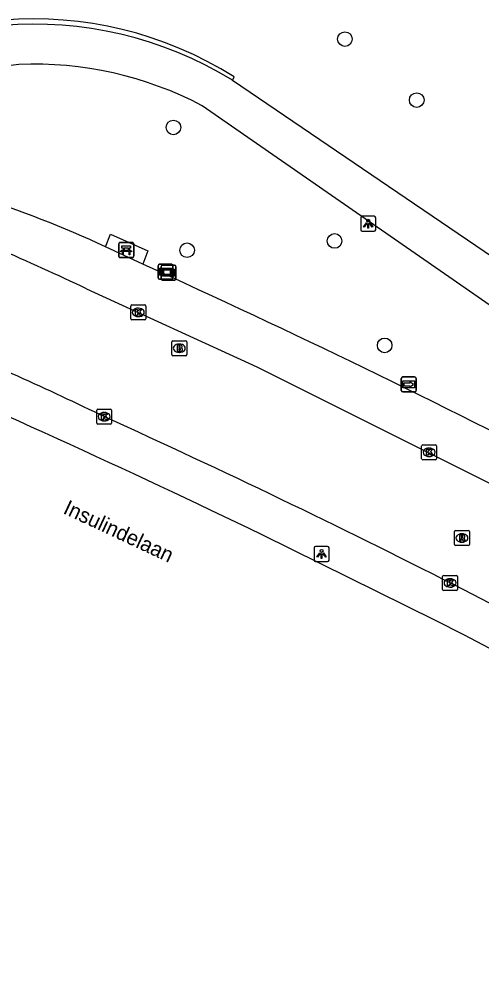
# Model space of a CAD drawing. Extents: x 162417 to 163721, y 384268 to 385416.
# Drawn here: x 162450.1 to 162481, y 384748.5 to 384811.7 of the extents above; entities that cross this region are included whole.
import ezdxf

# ---------------------------------------------------------------- set-up
doc = ezdxf.new("R2010")
doc.units = 0
for name, color, linetype in [('IMGEO_Bank', 7, 'Continuous'), ('IMGEO_Boom', 7, 'Continuous'), ('IMGEO_Brandkraan', 7, 'Continuous'), ('IMGEO_Kolk', 7, 'Continuous'), ('IMGEO_Lichtpunt', 7, 'Continuous'), ('IMGEO_Muur', 7, 'Continuous'), ('IMGEO_Openbare_ruimte_label', 7, 'Continuous'), ('IMGEO_Rijbaan_lokaal_open', 7, 'Continuous'), ('IMGEO_Rijbaan_regionaal_gesloten', 7, 'Continuous'), ('IMGEO_Rioolput', 7, 'Continuous'), ('IMGEO_Verklikker', 7, 'Continuous'), ('IMGEO_Voetpad_gesloten', 7, 'Continuous'), ('IMGEO_Voetpad_open', 7, 'Continuous'), ('IMGEO_Wegwijzer', 7, 'Continuous')]:
    doc.layers.add(name, color=color, linetype=linetype)

msp = doc.modelspace()

# ---------------------------------------------------------------- linework, layer by layer
at = {"layer": 'IMGEO_Bank'}
for p, q in [((162456.774, 384795.88), (162456.774, 384796.721)), ((162456.774, 384796.721), (162456.774, 384795.88)), ((162456.849, 384796.805), (162457.69, 384796.805)), ((162457.69, 384796.805), (162456.849, 384796.805)), ((162457.083, 384796.311), (162457.083, 384796.417)), ((162457.127, 384796.417), (162457.127, 384796.311)), ((162457.415, 384796.423), (162457.133, 384796.423)), ((162457.133, 384796.305), (162457.415, 384796.305)), ((162457.421, 384796.311), (162457.421, 384796.417)), ((162457.465, 384796.417), (162457.465, 384796.311)), ((162457.774, 384796.73), (162457.774, 384795.889)), ((162457.774, 384795.889), (162457.774, 384796.73)), ((162457.699, 384795.805), (162456.858, 384795.805)), ((162456.858, 384795.805), (162457.699, 384795.805)), ((162457.471, 384796.203), (162457.078, 384796.203))]:
    msp.add_line(p, q, dxfattribs=at)
for points in [[(162457.021, 384796.203), (162456.879, 384796.203), (162456.991, 384796.305), (162457.077, 384796.305)], [(162457.077, 384796.423), (162456.991, 384796.423), (162456.991, 384796.584), (162457.554, 384796.584), (162457.554, 384796.423), (162457.471, 384796.423)], [(162457.471, 384796.305), (162457.554, 384796.305), (162457.666, 384796.203), (162457.527, 384796.203)], [(162457.071, 384796.196), (162457.071, 384795.989), (162457.028, 384795.989), (162457.028, 384796.196)], [(162457.521, 384796.196), (162457.521, 384795.989), (162457.477, 384795.989), (162457.477, 384796.196)]]:
    msp.add_lwpolyline(points, dxfattribs=at)
for centre, radius, start, end in [((162456.852, 384796.727), 0.0779, 92.4484, 184.28452), ((162456.852, 384796.727), 0.0779, 92.4484, 184.28452), ((162457.076, 384796.416), 0.00671, 2.89567, 87.10433), ((162457.076, 384796.312), 0.00671, 272.89567, 357.10433), ((162457.133, 384796.416), 0.00671, 92.89567, 177.10433), ((162457.133, 384796.312), 0.00671, 182.89567, 267.10433), ((162457.415, 384796.416), 0.00671, 2.89567, 87.10433), ((162457.415, 384796.312), 0.00671, 272.89567, 357.10433), ((162457.472, 384796.416), 0.00671, 92.89567, 177.10433), ((162457.472, 384796.312), 0.00671, 182.89567, 267.10433), ((162457.696, 384796.727), 0.0779, 2.4484, 94.28452), ((162457.696, 384796.727), 0.0779, 2.4484, 94.28452), ((162456.852, 384795.883), 0.0779, 182.4484, 274.28452), ((162456.852, 384795.883), 0.0779, 182.4484, 274.28452), ((162457.021, 384796.196), 0.00671, 2.89567, 87.10433), ((162457.078, 384796.196), 0.00671, 92.89567, 177.10433), ((162457.47, 384796.196), 0.00671, 2.89567, 87.10433), ((162457.527, 384796.196), 0.00671, 92.89567, 177.10433), ((162457.696, 384795.883), 0.0779, 272.4484, 4.28452), ((162457.696, 384795.883), 0.0779, 272.4484, 4.28452)]:
    msp.add_arc(centre, radius, start, end, dxfattribs=at)
at = {"layer": 'IMGEO_Boom'}
for centre in [(162471.891, 384810.396), (162476.694, 384806.322), (162460.434, 384804.494), (162471.202, 384796.91), (162461.346, 384796.291), (162474.552, 384789.937)]:
    msp.add_circle(centre, 0.489, dxfattribs=at)
at = {"layer": 'IMGEO_Brandkraan'}
for p, q in [((162460.322, 384789.318), (162460.322, 384790.17)), ((162460.397, 384790.244), (162461.249, 384790.244)), ((162460.81, 384790.024), (162460.835, 384790.024)), ((162461.323, 384790.17), (162461.323, 384789.318)), ((162460.833, 384789.464), (162460.808, 384789.464)), ((162461.249, 384789.244), (162460.397, 384789.244))]:
    msp.add_line(p, q, dxfattribs=at)
for points in [[(162460.322, 384789.318), (162460.322, 384790.17)], [(162460.397, 384790.244), (162461.249, 384790.244)], [(162460.67, 384789.944), (162460.67, 384789.544), (162460.883, 384789.544)], [(162460.901, 384789.944), (162460.67, 384789.944)], [(162461.323, 384790.17), (162461.323, 384789.318)], [(162460.849, 384789.863), (162460.795, 384789.863), (162460.795, 384789.787)], [(162460.795, 384789.787), (162460.848, 384789.787)], [(162460.857, 384789.711), (162460.795, 384789.711), (162460.795, 384789.63)], [(162460.795, 384789.63), (162460.857, 384789.63)], [(162461.249, 384789.244), (162460.397, 384789.244)]]:
    msp.add_lwpolyline(points, dxfattribs=at)
for centre, radius, start, end in [((162460.399, 384790.168), 0.0765, 91.55205, 178.44795), ((162460.399, 384790.168), 0.0765, 91.55205, 178.44795), ((162460.905, 384789.799), 0.145, 59.4692, 91.53667), ((162460.93, 384789.846), 0.0922, 285.51372, 58.15012), ((162461.247, 384790.168), 0.0765, 1.55205, 88.44795), ((162461.247, 384790.168), 0.0765, 1.55205, 88.44795), ((162460.399, 384789.32), 0.0765, 181.55205, 268.44795), ((162460.399, 384789.32), 0.0765, 181.55205, 268.44795), ((162460.85, 384789.825), 0.0379, 267.82845, 90.93552), ((162460.858, 384789.67), 0.0404, 269.87594, 90.50774), ((162460.889, 384789.795), 0.251, 268.66757, 293.53466), ((162460.935, 384789.654), 0.105, 301.31148, 78.98903), ((162461.247, 384789.32), 0.0765, 271.55205, 358.44795), ((162461.247, 384789.32), 0.0765, 271.55205, 358.44795)]:
    msp.add_arc(centre, radius, start, end, dxfattribs=at)
for centre, major_axis, ratio, start_param, end_param in [((162460.809, 384789.744), (-0.387, 0.002), 0.722429, 4.712389, 7.853982), ((162460.834, 384789.744), (-0.39, 0.002), 0.717154, 1.570796, 4.712389)]:
    msp.add_ellipse(centre, major_axis=major_axis, ratio=ratio, start_param=start_param, end_param=end_param, dxfattribs=at)
at = {"layer": 'IMGEO_Kolk'}
for p, q in [((162457.583, 384791.714), (162457.583, 384792.566)), ((162457.658, 384792.64), (162458.51, 384792.64)), ((162458.584, 384792.566), (162458.584, 384791.714)), ((162458.094, 384791.86), (162458.069, 384791.86)), ((162458.071, 384792.42), (162458.096, 384792.42)), ((162458.51, 384791.64), (162457.658, 384791.64)), ((162455.3, 384784.745), (162455.3, 384785.597)), ((162455.375, 384785.671), (162456.227, 384785.671)), ((162456.301, 384785.597), (162456.301, 384784.745)), ((162455.811, 384784.891), (162455.786, 384784.891)), ((162455.788, 384785.451), (162455.813, 384785.451)), ((162456.227, 384784.671), (162455.375, 384784.671)), ((162477.025, 384782.366), (162477.025, 384783.218)), ((162477.1, 384783.292), (162477.952, 384783.292)), ((162477.513, 384783.072), (162477.538, 384783.072)), ((162478.026, 384783.218), (162478.026, 384782.366)), ((162477.536, 384782.512), (162477.511, 384782.512)), ((162477.952, 384782.292), (162477.1, 384782.292)), ((162478.426, 384773.637), (162478.426, 384774.489)), ((162478.501, 384774.563), (162479.353, 384774.563)), ((162478.914, 384774.343), (162478.939, 384774.343)), ((162479.427, 384774.489), (162479.427, 384773.637)), ((162479.353, 384773.563), (162478.501, 384773.563)), ((162478.937, 384773.783), (162478.912, 384773.783))]:
    msp.add_line(p, q, dxfattribs=at)
for points in [[(162457.583, 384791.714), (162457.583, 384792.566)], [(162457.658, 384792.64), (162458.51, 384792.64)], [(162458.584, 384792.566), (162458.584, 384791.714)], [(162457.904, 384792.34), (162458.027, 384792.34), (162458.027, 384792.189), (162458.157, 384792.34), (162458.321, 384792.34), (162458.175, 384792.189), (162458.328, 384791.94), (162458.176, 384791.94), (162458.091, 384792.104), (162458.027, 384792.037), (162458.027, 384791.94), (162457.904, 384791.94), (162457.904, 384792.34)], [(162458.51, 384791.64), (162457.658, 384791.64)], [(162455.3, 384784.745), (162455.3, 384785.597)], [(162455.375, 384785.671), (162456.227, 384785.671)], [(162456.301, 384785.597), (162456.301, 384784.745)], [(162455.621, 384785.371), (162455.744, 384785.371), (162455.744, 384785.22), (162455.874, 384785.371), (162456.038, 384785.371), (162455.892, 384785.22), (162456.045, 384784.971), (162455.893, 384784.971), (162455.808, 384785.135), (162455.744, 384785.068), (162455.744, 384784.971), (162455.621, 384784.971), (162455.621, 384785.371)], [(162456.227, 384784.671), (162455.375, 384784.671)], [(162477.025, 384782.366), (162477.025, 384783.218)], [(162477.1, 384783.292), (162477.952, 384783.292)], [(162477.346, 384782.992), (162477.469, 384782.992), (162477.469, 384782.841), (162477.599, 384782.992), (162477.763, 384782.992), (162477.617, 384782.841), (162477.77, 384782.592), (162477.618, 384782.592), (162477.533, 384782.756), (162477.469, 384782.689), (162477.469, 384782.592), (162477.346, 384782.592), (162477.346, 384782.992)], [(162478.026, 384783.218), (162478.026, 384782.366)], [(162477.952, 384782.292), (162477.1, 384782.292)], [(162478.426, 384773.637), (162478.426, 384774.489)], [(162478.501, 384774.563), (162479.353, 384774.563)], [(162478.747, 384774.263), (162478.87, 384774.263), (162478.87, 384774.112), (162479, 384774.263), (162479.164, 384774.263), (162479.018, 384774.112), (162479.171, 384773.863), (162479.019, 384773.863), (162478.934, 384774.027), (162478.87, 384773.96), (162478.87, 384773.863), (162478.747, 384773.863), (162478.747, 384774.263)], [(162479.427, 384774.489), (162479.427, 384773.637)], [(162479.353, 384773.563), (162478.501, 384773.563)]]:
    msp.add_lwpolyline(points, dxfattribs=at)
for centre, start, end in [((162457.66, 384792.564), 91.55205, 178.44795), ((162457.66, 384792.564), 91.55205, 178.44795), ((162458.508, 384792.564), 1.55205, 88.44795), ((162458.508, 384792.564), 1.55205, 88.44795), ((162457.66, 384791.716), 181.55205, 268.44795), ((162457.66, 384791.716), 181.55205, 268.44795), ((162458.508, 384791.716), 271.55205, 358.44795), ((162458.508, 384791.716), 271.55205, 358.44795), ((162455.377, 384785.595), 91.55205, 178.44795), ((162455.377, 384785.595), 91.55205, 178.44795), ((162456.225, 384785.595), 1.55205, 88.44795), ((162456.225, 384785.595), 1.55205, 88.44795), ((162455.377, 384784.747), 181.55205, 268.44795), ((162455.377, 384784.747), 181.55205, 268.44795), ((162456.225, 384784.747), 271.55205, 358.44795), ((162456.225, 384784.747), 271.55205, 358.44795), ((162477.102, 384783.216), 91.55205, 178.44795), ((162477.102, 384783.216), 91.55205, 178.44795), ((162477.95, 384783.216), 1.55205, 88.44795), ((162477.95, 384783.216), 1.55205, 88.44795), ((162477.102, 384782.368), 181.55205, 268.44795), ((162477.102, 384782.368), 181.55205, 268.44795), ((162477.95, 384782.368), 271.55205, 358.44795), ((162477.95, 384782.368), 271.55205, 358.44795), ((162478.503, 384774.487), 91.55205, 178.44795), ((162478.503, 384774.487), 91.55205, 178.44795), ((162479.351, 384774.487), 1.55205, 88.44795), ((162479.351, 384774.487), 1.55205, 88.44795), ((162478.503, 384773.639), 181.55205, 268.44795), ((162478.503, 384773.639), 181.55205, 268.44795), ((162479.351, 384773.639), 271.55205, 358.44795), ((162479.351, 384773.639), 271.55205, 358.44795)]:
    msp.add_arc(centre, 0.0765, start, end, dxfattribs=at)
for centre, major_axis, ratio, start_param, end_param in [((162458.07, 384792.14), (-0.387, 0.002), 0.722429, 4.712389, 7.853982), ((162458.095, 384792.14), (-0.39, 0.002), 0.717154, 1.570796, 4.712389), ((162455.787, 384785.171), (-0.387, 0.002), 0.722429, 4.712389, 7.853982), ((162455.812, 384785.171), (-0.39, 0.002), 0.717154, 1.570796, 4.712389), ((162477.512, 384782.792), (-0.387, 0.002), 0.722429, 4.712389, 7.853982), ((162477.537, 384782.792), (-0.39, 0.002), 0.717154, 1.570796, 4.712389), ((162478.913, 384774.063), (-0.387, 0.002), 0.722429, 4.712389, 7.853982), ((162478.938, 384774.063), (-0.39, 0.002), 0.717154, 1.570796, 4.712389)]:
    msp.add_ellipse(centre, major_axis=major_axis, ratio=ratio, start_param=start_param, end_param=end_param, dxfattribs=at)
at = {"layer": 'IMGEO_Lichtpunt'}
for p, q in [((162472.955, 384798.462), (162472.955, 384797.655)), ((162472.955, 384798.462), (162472.955, 384797.655)), ((162473.857, 384798.557), (162473.049, 384798.557)), ((162473.857, 384798.557), (162473.049, 384798.557)), ((162473.951, 384797.655), (162473.951, 384798.462)), ((162473.951, 384797.655), (162473.951, 384798.462)), ((162473.049, 384797.561), (162473.857, 384797.561)), ((162473.049, 384797.561), (162473.857, 384797.561)), ((162469.836, 384776.404), (162469.836, 384775.597)), ((162469.836, 384776.404), (162469.836, 384775.597)), ((162470.738, 384776.499), (162469.93, 384776.499)), ((162470.738, 384776.499), (162469.93, 384776.499)), ((162470.832, 384775.597), (162470.832, 384776.404)), ((162470.832, 384775.597), (162470.832, 384776.404)), ((162469.93, 384775.503), (162470.738, 384775.503)), ((162469.93, 384775.503), (162470.738, 384775.503))]:
    msp.add_line(p, q, dxfattribs=at)
for points in [[(162473.329, 384798.126), (162473.368, 384798.098), (162473.18, 384797.836), (162473.142, 384797.863), (162473.329, 384798.126)], [(162473.541, 384798.098), (162473.579, 384798.125), (162473.766, 384797.863), (162473.727, 384797.835), (162473.541, 384798.098)], [(162473.431, 384798.078), (162473.478, 384798.078), (162473.478, 384797.756), (162473.431, 384797.756), (162473.431, 384798.078)], [(162470.21, 384776.068), (162470.249, 384776.04), (162470.061, 384775.778), (162470.023, 384775.805), (162470.21, 384776.068)], [(162470.312, 384776.02), (162470.359, 384776.02), (162470.359, 384775.698), (162470.312, 384775.698), (162470.312, 384776.02)], [(162470.422, 384776.04), (162470.46, 384776.067), (162470.647, 384775.805), (162470.608, 384775.777), (162470.422, 384776.04)]]:
    msp.add_lwpolyline(points, dxfattribs=at)
for centre in [(162473.454, 384798.26), (162470.335, 384776.202)]:
    msp.add_circle(centre, 0.0994, dxfattribs=at)
for centre, start, end in [((162473.049, 384798.462), 90, 180), ((162473.049, 384798.462), 90, 180), ((162473.857, 384798.462), 0, 90), ((162473.857, 384798.462), 0, 90), ((162473.049, 384797.655), 180, 270), ((162473.049, 384797.655), 180, 270), ((162473.857, 384797.655), 270, 0), ((162473.857, 384797.655), 270, 360), ((162469.93, 384776.404), 90, 180), ((162469.93, 384776.404), 90, 180), ((162470.738, 384776.404), 0, 90), ((162470.738, 384776.404), 0, 90), ((162469.93, 384775.597), 180, 270), ((162469.93, 384775.597), 180, 270), ((162470.738, 384775.597), 270, 0), ((162470.738, 384775.597), 270, 360)]:
    msp.add_arc(centre, 0.0946, start, end, dxfattribs=at)
at = {"layer": 'IMGEO_Muur'}
msp.add_lwpolyline([(162464.374, 384807.642), (162464.494, 384807.871)], dxfattribs=at)
for centre, radius, start, end in [((162451.106, 384786.674), 25.071, 57.72343, 131.48636), ((162451.157, 384786.209), 25.181, 58.33975, 131.26956)]:
    msp.add_arc(centre, radius, start, end, dxfattribs=at)
at = {"layer": 'IMGEO_Rijbaan_lokaal_open'}
for points in [[(162454.631, 384793.723), (162466.003, 384788.506), (162484.372, 384779.337), (162491.246, 384775.872), (162492.146, 384775.425), (162493.067, 384775.022)], [(162489.507, 384768.547), (162481.057, 384772.976), (162479.187, 384773.932)]]:
    msp.add_lwpolyline(points, dxfattribs=at)
for centre, radius, start, end in [((162282.585, 384421.095), 410.429, 65.21685, 67.0318), ((162360.374, 384588.343), 218.744, 64.1108, 67.49915), ((162220.047, 384264.715), 571.363, 63.02849, 65.62141)]:
    msp.add_arc(centre, radius, start, end, dxfattribs=at)
at = {"layer": 'IMGEO_Rijbaan_regionaal_gesloten'}
msp.add_lwpolyline([(162519.432, 384748.535), (162518.198, 384749.269), (162516.963, 384750), (162500, 384759.787), (162493.238, 384763.558), (162479.839, 384770.588), (162477.959, 384771.545), (162466.355, 384777.285)], dxfattribs=at)
msp.add_arc((162146.963, 384113.728), 736.423, 64.296966, 66.648497, dxfattribs=at)
at = {"layer": 'IMGEO_Rioolput'}
for p, q in [((162479.215, 384776.641), (162479.215, 384777.493)), ((162479.29, 384777.567), (162480.142, 384777.567)), ((162479.703, 384777.347), (162479.728, 384777.347)), ((162480.216, 384777.493), (162480.216, 384776.641)), ((162479.726, 384776.787), (162479.701, 384776.787)), ((162480.142, 384776.567), (162479.29, 384776.567))]:
    msp.add_line(p, q, dxfattribs=at)
for points in [[(162479.215, 384776.641), (162479.215, 384777.493)], [(162479.29, 384777.567), (162480.142, 384777.567)], [(162479.804, 384777.265), (162479.552, 384777.267), (162479.552, 384776.867)], [(162480.216, 384777.493), (162480.216, 384776.641)], [(162479.552, 384776.867), (162479.676, 384776.867), (162479.676, 384777.029), (162479.687, 384777.029)], [(162479.73, 384777.186), (162479.676, 384777.186), (162479.676, 384777.105)], [(162479.676, 384777.105), (162479.728, 384777.105)], [(162479.734, 384777), (162479.805, 384776.867), (162479.945, 384776.867), (162479.88, 384776.993)], [(162480.142, 384776.567), (162479.29, 384776.567)]]:
    msp.add_lwpolyline(points, dxfattribs=at)
for centre, radius, start, end in [((162479.292, 384777.491), 0.0765, 91.55205, 178.44795), ((162479.292, 384777.491), 0.0765, 91.55205, 178.44795), ((162479.803, 384777.155), 0.109, 350.36119, 89.41601), ((162480.14, 384777.491), 0.0765, 1.55205, 88.44795), ((162480.14, 384777.491), 0.0765, 1.55205, 88.44795), ((162479.292, 384776.643), 0.0765, 181.55205, 268.44795), ((162479.292, 384776.643), 0.0765, 181.55205, 268.44795), ((162479.686, 384776.976), 0.0533, 26.02933, 88.69889), ((162479.712, 384777.294), 0.19, 274.7715, 282.96867), ((162479.736, 384777.09), 0.0964, 77.00612, 93.18647), ((162479.75, 384777.147), 0.0378, 276.66336, 79.67722), ((162479.801, 384777.155), 0.112, 277.58423, 350.98172), ((162479.785, 384776.94), 0.108, 29.51342, 73.79051), ((162480.14, 384776.643), 0.0765, 271.55205, 358.44795), ((162480.14, 384776.643), 0.0765, 271.55205, 358.44795)]:
    msp.add_arc(centre, radius, start, end, dxfattribs=at)
for centre, major_axis, ratio, start_param, end_param in [((162479.702, 384777.067), (-0.387, 0.002), 0.722429, 4.712389, 7.853982), ((162479.727, 384777.067), (-0.39, 0.002), 0.717154, 1.570796, 4.712389)]:
    msp.add_ellipse(centre, major_axis=major_axis, ratio=ratio, start_param=start_param, end_param=end_param, dxfattribs=at)
at = {"layer": 'IMGEO_Verklikker'}
for p, q in [((162459.407, 384794.456), (162459.407, 384795.256)), ((162459.407, 384795.256), (162459.407, 384794.456)), ((162459.507, 384795.356), (162460.297, 384795.356)), ((162460.297, 384795.356), (162459.507, 384795.356)), ((162459.61, 384794.4), (162459.61, 384795.2)), ((162459.61, 384795.2), (162459.61, 384794.4)), ((162459.71, 384795.3), (162460.5, 384795.3)), ((162460.5, 384795.3), (162459.71, 384795.3)), ((162460.397, 384795.256), (162460.397, 384794.456)), ((162460.397, 384794.456), (162460.397, 384795.256)), ((162460.6, 384795.2), (162460.6, 384794.4)), ((162460.6, 384794.4), (162460.6, 384795.2)), ((162460.297, 384794.356), (162459.507, 384794.356)), ((162459.507, 384794.356), (162460.297, 384794.356)), ((162460.5, 384794.3), (162459.71, 384794.3)), ((162459.71, 384794.3), (162460.5, 384794.3))]:
    msp.add_line(p, q, dxfattribs=at)
for points in [[(162459.508, 384795.088), (162460.296, 384795.088), (162460.296, 384794.624), (162459.508, 384794.624), (162459.508, 384795.088)], [(162459.573, 384795.023), (162459.573, 384794.689), (162460.231, 384794.689), (162460.231, 384795.023), (162459.573, 384795.023)], [(162459.711, 384795.032), (162460.499, 384795.032), (162460.499, 384794.568), (162459.711, 384794.568), (162459.711, 384795.032)], [(162459.776, 384794.967), (162459.776, 384794.633), (162460.434, 384794.633), (162460.434, 384794.967), (162459.776, 384794.967)]]:
    msp.add_lwpolyline(points, dxfattribs=at)
for centre, start, end in [((162459.507, 384795.256), 90, 180), ((162459.507, 384795.256), 90, 180), ((162459.71, 384795.2), 90, 180), ((162459.71, 384795.2), 90, 180), ((162460.297, 384795.256), 0, 90), ((162460.297, 384795.256), 360, 90), ((162460.5, 384795.2), 0, 90), ((162460.5, 384795.2), 360, 90), ((162459.507, 384794.456), 180, 270), ((162459.507, 384794.456), 180, 270), ((162459.71, 384794.4), 180, 270), ((162459.71, 384794.4), 180, 270), ((162460.297, 384794.456), 270, 0), ((162460.297, 384794.456), 270, 0), ((162460.5, 384794.4), 270, 0), ((162460.5, 384794.4), 270, 0)]:
    msp.add_arc(centre, 0.1, start, end, dxfattribs=at)
at = {"layer": 'IMGEO_Voetpad_gesloten'}
for points in [[(162455.897, 384796.521), (162456.22, 384797.372), (162458.722, 384796.241), (162458.39, 384795.353)], [(162458.39, 384795.353), (162455.897, 384796.521)]]:
    msp.add_lwpolyline(points, dxfattribs=at)
at = {"layer": 'IMGEO_Voetpad_open'}
for points in [[(162450.102, 384808.704), (162449.025, 384808.568)], [(162490.519, 384789.889), (162464.374, 384807.642)], [(162499.083, 384780.528), (162490.839, 384786.198), (162462.348, 384805.947)]]:
    msp.add_lwpolyline(points, dxfattribs=at)
for centre, radius, start, end in [((162451.116, 384784.633), 24.092, 62.2119, 92.41264), ((162425.647, 384731.569), 71.651, 65.02731, 72.50406), ((162202.838, 384231.055), 619.467, 62.609428, 65.635797)]:
    msp.add_arc(centre, radius, start, end, dxfattribs=at)
at = {"layer": 'IMGEO_Wegwijzer'}
for p, q in [((162475.664, 384786.925), (162475.664, 384787.725)), ((162475.664, 384787.725), (162475.664, 384786.925)), ((162475.764, 384787.825), (162476.554, 384787.825)), ((162476.554, 384787.825), (162475.764, 384787.825)), ((162476.654, 384787.725), (162476.654, 384786.925)), ((162476.654, 384786.925), (162476.654, 384787.725)), ((162476.554, 384786.825), (162475.764, 384786.825)), ((162475.764, 384786.825), (162476.554, 384786.825))]:
    msp.add_line(p, q, dxfattribs=at)
for points in [[(162475.765, 384787.557), (162476.553, 384787.557), (162476.553, 384787.093), (162475.765, 384787.093), (162475.765, 384787.557)], [(162475.83, 384787.409), (162475.83, 384787.325), (162475.83, 384787.241), (162476.241, 384787.241), (162476.241, 384787.158), (162476.488, 384787.325), (162476.241, 384787.492), (162476.241, 384787.409), (162475.83, 384787.409)]]:
    msp.add_lwpolyline(points, dxfattribs=at)
for centre, start, end in [((162475.764, 384787.725), 90, 180), ((162475.764, 384787.725), 90, 180), ((162476.554, 384787.725), 0, 90), ((162476.554, 384787.725), 360, 90), ((162475.764, 384786.925), 180, 270), ((162475.764, 384786.925), 180, 270), ((162476.554, 384786.925), 270, 0), ((162476.554, 384786.925), 270, 0)]:
    msp.add_arc(centre, 0.1, start, end, dxfattribs=at)

# ---------------------------------------------------------------- texts
at = {"layer": 'IMGEO_Openbare_ruimte_label'}
msp.add_text('Insulindelaan', height=1, rotation=334.92082, dxfattribs=at).set_placement((162452.997, 384778.739))

doc.saveas('drawing.dxf')
